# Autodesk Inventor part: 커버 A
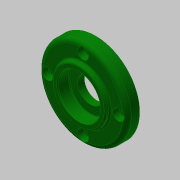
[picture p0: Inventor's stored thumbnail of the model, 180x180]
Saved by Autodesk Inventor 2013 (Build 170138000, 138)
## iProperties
Created: 2019-01
Part Number: 커버 A
Material: 알루미늄 6061
Document SubType Name: Modeling
Designer: mduedu
Density: 1 g/cm^3
Author: mduedu
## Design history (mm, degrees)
sketch "스케치1"
  geometry: L1 (0, 0)-(9, 0); L2 (9, 0)-(9, 31); L3 (9, 31)-(0, 31); L4 (0, 31)-(0, 0); L5 (9, 0)-(13, 0); L6 (13, 0)-(13, 20); L7 (13, 20)-(9, 20); L8 (9, 20)-(9, 0)
  constraints: 16 end point, 4 parallel, 2 horizontal, 2 perpendicular
  dimensions: "d0" = 13 distance between parallel lines of L6 L4; "d2" = 62 diameter of L3 L1; "d3" = 40 diameter of L7 L5; "d4" = 4 distance between parallel lines of L6 L2
revolve "회전1" sketch "스케치1" stored, may be unused: angle "d5" = 90 deg
sketch "스케치5"
  geometry: C1 r 19 at (0, 0); 1 further point
  constraints: 1 centre point, 1 coincident
  dimensions: "d34" = 38 diameter of C1
extrude "돌출1" join sketch "스케치5" distance "d35" = 3; taper "d36" = 0 deg
sketch "스케치2"
  geometry: L1 (9, -20)-(9, -31) reference; L2 (9, -31)-(0, -31) reference; L3 (0, -31)-(0, -19) reference; L4 (0, -19)-(-3, -19) reference; L5 (-3, -19)-(-3, 19) reference; L6 (-3, 19)-(0, 19) reference; L7 (0, 19)-(0, 31) reference; L8 (0, 31)-(9, 31) reference; L9 (9, 31)-(9, 20) reference; L10 (9, 20)-(13, 20) reference; L11 (13, 20)-(13, -20) reference; L12 (13, -20)-(9, -20) reference; L13 (-3, 0)-(5.3, 0); L14 (5.3, 0)-(5.3, 15); L15 (5.3, 15)-(-3, 15); L16 (-3, 15)-(-3, 0); L17 (5.3, 0)-(10, 0); L18 (10, 0)-(10, 9); L19 (10, 9)-(5.3, 9); L20 (5.3, 9)-(5.3, 0); L21 (10, 0)-(13, 0); L22 (13, 0)-(13, 15); L23 (13, 15)-(10, 15); L24 (10, 15)-(10, 0)
  constraints: 24 end point, 6 parallel, 3 horizontal, 3 perpendicular, 1 midpoint, 1 point on line
  dimensions: "d38" = 30 diameter of L15 L13; "d40" = 30 diameter of L23 L21; "d41" = 3 distance of L22.end L23.end; "d42" = 8.3 distance of L14.end L15.end; "d43" = 18 diameter of L19 L17
revolve "회전2" sketch "스케치2" stored, may be unused: angle "d12" = 90 deg
chamfer "모따기1" distance "d13" = 0.8; stored, may be unused: second distance "d14" = 2, angle "d15" = 30 deg
fillet "모깎기1" dims "d16" = 0.5
fillet "모깎기2" dims "d17" = 3
fillet "모깎기3" dims "d18" = 3
chamfer "모따기2" distance "d24" = 1; stored, may be unused: second distance "d25" = 2, angle "d26" = 45 deg
sketch "스케치3" dims "d19" = 50
  geometry: 6 further points
  constraints: 2 vertical alignment, 1 coincident, 7 other
  dimensions: "d22" = 360 deg dimension on point (0, 0) point (0, 25) (derived)
sketch "스케치4"
  geometry: 4 further points
  constraints: 4 other
hole "구멍1" sketch "스케치4" at (-25, 0), (0, -25), (25, 0), (0, 25) diameter "d27" = 4.5; stored, may be unused: countersink angle "d31" = 90 deg, drill point angle "d33" = 0 deg; dims "d28" = 6, "d29" = 8, "d30" = 4.6, "d32" = 8
fillet "모깎기6" dims "d47" = 1
node "솔리드1"
node "절단 모서리 투영2"
